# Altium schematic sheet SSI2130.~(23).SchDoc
size Letter
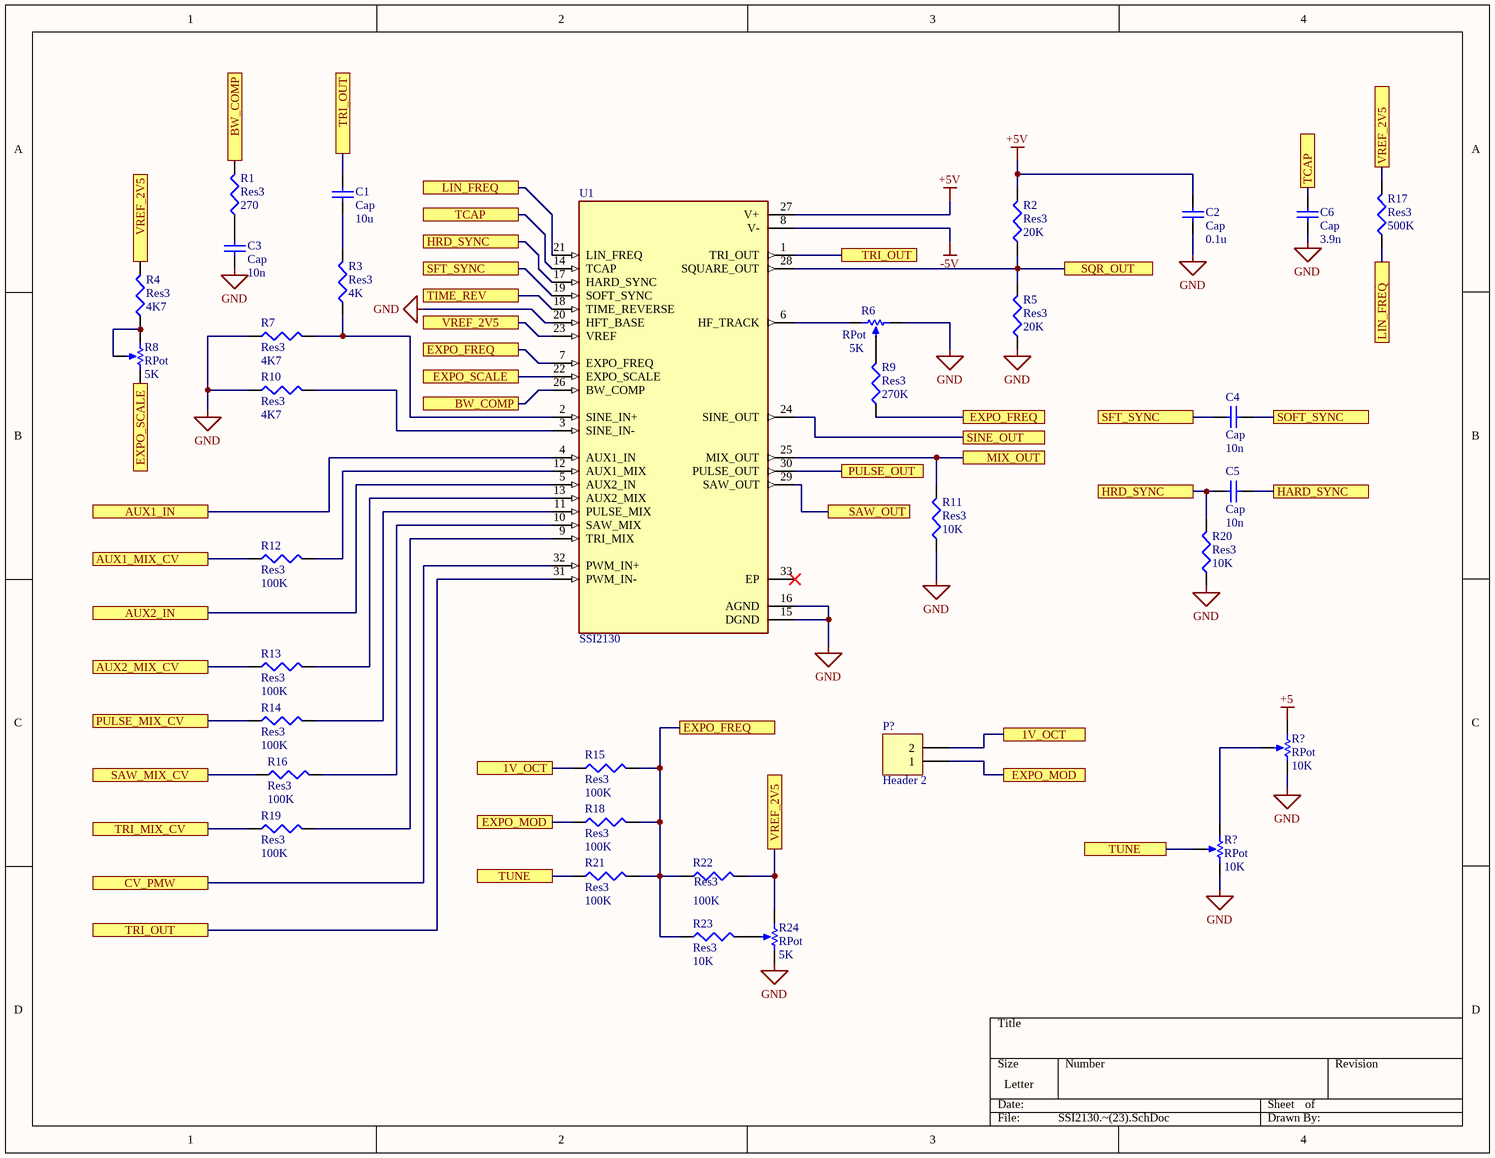
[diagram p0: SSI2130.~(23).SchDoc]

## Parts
(Parts that share a designator on the sheet are numbered #1, #2 ... from top to bottom, then left to right.)
C1  Cap  value 10u  [RAD-0.3]
C2  Cap  value 0.1u  [RAD-0.3]
C3  Cap  value 10n  [RAD-0.3]
C4  Cap  value 10n  [RAD-0.3]
C5  Cap  value 10n  [RAD-0.3]
C6  Cap  value 3.9n  [RAD-0.3]
P?  Header 2  [HDR1X2]
R1  Res3  value 270  [J1-0603]
R2  Res3  value 20K  [J1-0603]
R3  Res3  value 4K  [J1-0603]
R4  Res3  value 4K7  [J1-0603]
R5  Res3  value 20K  [J1-0603]
R6  RPot  value 5K  [VR5]
R7  Res3  value 4K7  [J1-0603]
R8  RPot  value 5K  [VR5]
R9  Res3  value 270K  [J1-0603]
R10  Res3  value 4K7  [J1-0603]
R11  Res3  value 10K  [J1-0603]
R12  Res3  value 100K  [J1-0603]
R13  Res3  value 100K  [J1-0603]
R14  Res3  value 100K  [J1-0603]
R15  Res3  value 100K  [J1-0603]
R16  Res3  value 100K  [J1-0603]
R17  Res3  value 500K  [J1-0603]
R18  Res3  value 100K  [J1-0603]
R19  Res3  value 100K  [J1-0603]
R20  Res3  value 10K  [J1-0603]
R21  Res3  value 100K  [J1-0603]
R22  Res3  value 100K  [J1-0603]
R23  Res3  value 10K  [J1-0603]
R24  RPot  value 5K  [VR5]
R?#1  RPot  value 10K  [VR5]
R?#2  RPot  value 10K  [VR5]
U1  SSI2130  [QFN40P400X400X90-33N]

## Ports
1V_OCT, AUX1_IN, AUX1_MIX_CV, AUX2_IN, AUX2_MIX_CV, BW_COMP, CV_PMW, EXPO_FREQ, EXPO_MOD, EXPO_SCALE, HARD_SYNC, HRD_SYNC, LIN_FREQ, MIX_OUT, PULSE_MIX_CV, PULSE_OUT, SAW_MIX_CV, SAW_OUT, SFT_SYNC, SINE_OUT, SOFT_SYNC, SQR_OUT, TCAP, TIME_REV, TRI_MIX_CV, TRI_OUT, TUNE, VREF_2V5

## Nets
+5: R?#1.1(TOP)
+5V: C2.2 R2.2 U1.27(V+)
-5V: U1.8(V-)
GND: C2.1 C3.1 C6.1 R5.1 R6.2(BOT) R7.1 R10.1 R11.1 R20.1 R24.2(BOT) R?#1.2(BOT) R?#2.2(BOT) U1.15(DGND) U1.16(AGND) U1.20(HFT_BASE)
1V_OCT: P?.2 R15.1 ; port 1V_OCT
AUX1_IN: U1.4(AUX1_IN) ; port AUX1_IN
AUX1_MIX_CV: R12.1 ; port AUX1_MIX_CV
AUX2_IN: U1.5(AUX2_IN) ; port AUX2_IN
AUX2_MIX_CV: R13.1 ; port AUX2_MIX_CV
BW_COMP: R1.2 U1.26(BW_COMP) ; port BW_COMP
CV_PMW: U1.32(PWM_IN+) ; port CV_PMW
EXPO_FREQ: R9.1 R15.2 R18.2 R21.2 R22.1 R23.1 U1.7(EXPO_FREQ) ; port EXPO_FREQ
EXPO_MOD: P?.1 R18.1 ; port EXPO_MOD
EXPO_SCALE: R8.2(BOT) U1.22(EXPO_SCALE) ; port EXPO_SCALE
HARD_SYNC: C5.2 ; port HARD_SYNC
HRD_SYNC: C5.1 R20.2 U1.17(HARD_SYNC) ; port HRD_SYNC
LIN_FREQ: R17.1 U1.21(LIN_FREQ) ; port LIN_FREQ
MIX_OUT: R11.2 U1.25(MIX_OUT) ; port MIX_OUT
PULSE_MIX_CV: R14.1 ; port PULSE_MIX_CV
PULSE_OUT: U1.30(PULSE_OUT) ; port PULSE_OUT
SAW_MIX_CV: R16.1 ; port SAW_MIX_CV
SAW_OUT: U1.29(SAW_OUT) ; port SAW_OUT
SFT_SYNC: C4.1 U1.19(SOFT_SYNC) ; port SFT_SYNC
SINE_OUT: U1.24(SINE_OUT) ; port SINE_OUT
SOFT_SYNC: C4.2 ; port SOFT_SYNC
SQR_OUT: R2.1 R5.2 U1.28(SQUARE_OUT) ; port SQR_OUT
TCAP: C6.2 U1.14(TCAP) ; port TCAP
TIME_REV: U1.18(TIME_REVERSE) ; port TIME_REV
TRI_MIX_CV: R19.1 ; port TRI_MIX_CV
TRI_OUT: C1.2 U1.1(TRI_OUT) U1.31(PWM_IN-) ; port TRI_OUT
TUNE: R21.1 R?#2.3(TAP) ; port TUNE
VREF_2V5: R4.2 R17.2 R22.2 R24.1(TOP) U1.23(VREF) ; port VREF_2V5
NetC1_1: C1.1 R3.2
NetC3_2: C3.2 R1.1
NetR3_1: R3.1 R7.2 U1.2(SINE_IN+)
NetR4_1: R4.1 R8.1(TOP) R8.3(TAP)
NetR6_1: R6.1(TOP) U1.6(HF_TRACK)
NetR6_3: R6.3(TAP) R9.2
NetR10_2: R10.2 U1.3(SINE_IN-)
NetR12_2: R12.2 U1.12(AUX1_MIX)
NetR13_2: R13.2 U1.13(AUX2_MIX)
NetR14_2: R14.2 U1.11(PULSE_MIX)
NetR16_2: R16.2 U1.10(SAW_MIX)
NetR19_2: R19.2 U1.9(TRI_MIX)
NetR23_2: R23.2 R24.3(TAP)
NetR?#1_3: R?#1.3(TAP) R?#2.1(TOP)

Not connected (* = marked no-connect by the designer): U1 33(EP)*

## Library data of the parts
C1-C6 = Cap: Capacitor
P? = Header 2: Header, 2-Pin
R1-R5 R7 R9-R23 = Res3: Resistor
R6 R8 R24 R?#1 R?#2 = RPot: Potentiometer; Sim Note: Enter the Resistance value and the set point into parameter fields.; Set Position: 0.5
U1 = SSI2130: Voltage controlled oscillator subsystem for high-performance electronic musical instruments; MF: Sound Semiconductor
